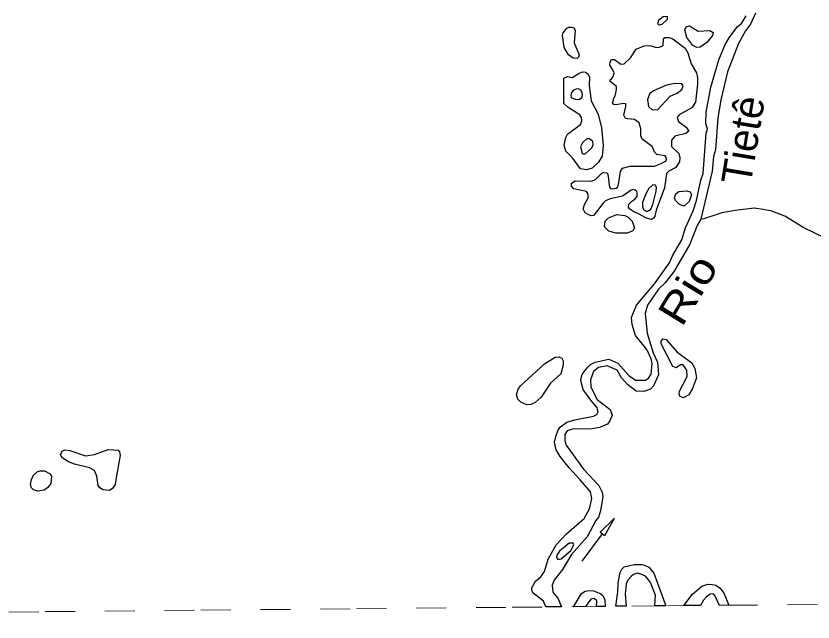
# Model space of a CAD drawing. Extents: x 346.5 to 372.4, y 7400.3 to 7428.2.
# Drawn here: x 361.849 to 364.517, y 7400.435 to 7402.464 of the extents above; entities that cross this region are included whole.
import ezdxf
from ezdxf.enums import TextEntityAlignment as Align

# ---------------------------------------------------------------- set-up
doc = ezdxf.new("R2010")
doc.units = 0
doc.header["$LTSCALE"] = 0.032
doc.linetypes.add('SHORT_DASHED', pattern=[2.7, 1.5, -1.2])
for name, color, linetype, lineweight in [('10', 7, 'Continuous', 25), ('2', 7, 'Continuous', 25), ('53', 7, 'SHORT_DASHED', 13), ('7', 7, 'Continuous', 25)]:
    doc.layers.add(name, color=color, linetype=linetype, lineweight=lineweight)
doc.layers.add('61', color=7, linetype='Continuous')

msp = doc.modelspace()

# ---------------------------------------------------------------- linework, layer by layer
at = {"layer": '10'}
msp.add_line((363.7437, 7400.6394), (363.8123, 7400.7301), dxfattribs=at)
msp.add_lwpolyline([(363.8526, 7400.7834), (363.8048, 7400.7359), (363.8199, 7400.7244)], close=True, dxfattribs=at)
at = {"layer": '2'}
for points in [[(364.3242, 7402.4731), (364.3184, 7402.4604), (364.3078, 7402.4359), (364.2912, 7402.4137), (364.2675, 7402.3718), (364.23, 7402.2764), (364.2086, 7402.183), (364.1981, 7402.1215), (364.1905, 7402.0154), (364.1833, 7401.9939), (364.1787, 7401.9447), (364.1416, 7401.7836), (364.1286, 7401.7624), (364.1045, 7401.6998), (364.0522, 7401.6091), (364.022, 7401.5709), (364, 7401.5495), (363.9624, 7401.496), (363.9552, 7401.4676), (363.9615, 7401.4019), (363.9814, 7401.3367), (363.9963, 7401.3045), (364, 7401.2624), (363.9834, 7401.226), (363.9725, 7401.215), (363.9505, 7401.2066), (363.9248, 7401.2083), (363.8953, 7401.2306), (363.8761, 7401.2527), (363.8618, 7401.2784), (363.828, 7401.2931), (363.799, 7401.2875), (363.7823, 7401.2734), (363.7715, 7401.2459), (363.7737, 7401.2214), (363.7939, 7401.1805), (363.8381, 7401.1462), (363.8447, 7401.1282), (363.8372, 7401.1087), (363.8287, 7401.0977), (363.8027, 7401.086), (363.7704, 7401.0811), (363.7148, 7401.0817), (363.6944, 7401.0747), (363.6861, 7401.0626), (363.6859, 7401.0415), (363.6911, 7401.0273), (363.7486, 7400.9474), (363.7996, 7400.8926), (363.8109, 7400.8698), (363.8137, 7400.8549), (363.8058, 7400.8072), (363.7985, 7400.7858), (363.7896, 7400.7755), (363.7612, 7400.7208), (363.7087, 7400.661), (363.6786, 7400.6106), (363.65, 7400.575), (363.6438, 7400.5587), (363.6463, 7400.5351), (363.6625, 7400.5148), (363.6752, 7400.4862), (363.6224, 7400.4857), (363.6143, 7400.5054), (363.579, 7400.5329), (363.5752, 7400.5414), (363.5757, 7400.5503), (363.5881, 7400.5716), (363.6054, 7400.5866), (363.6185, 7400.6042), (363.6305, 7400.6461), (363.6571, 7400.6934), (363.6919, 7400.7306), (363.7505, 7400.7817), (363.7686, 7400.8145), (363.7768, 7400.8493), (363.7718, 7400.8712), (363.7375, 7400.9111), (363.7008, 7400.9509), (363.6706, 7400.9891), (363.6575, 7401.0114), (363.6517, 7401.0373), (363.6557, 7401.0568), (363.6633, 7401.0784), (363.6719, 7401.0886), (363.693, 7401.1044), (363.7195, 7401.1124), (363.7825, 7401.1238), (363.7937, 7401.1304), (363.7979, 7401.1389), (363.7948, 7401.1518), (363.7727, 7401.1777)], [(363.7727, 7401.1777), (363.747, 7401.2141), (363.7408, 7401.2391), (363.7398, 7401.2471), (363.7442, 7401.2633), (363.7593, 7401.2855), (363.7722, 7401.2974), (363.7879, 7401.3051), (363.8331, 7401.3147), (363.8636, 7401.3015), (363.9002, 7401.2605), (363.9231, 7401.245), (363.9558, 7401.2445), (363.966, 7401.252), (363.9748, 7401.2649), (363.978, 7401.3001), (363.975, 7401.3157), (363.961, 7401.3479), (363.9228, 7401.3941), (363.9114, 7401.4308), (363.9092, 7401.4542), (363.9265, 7401.4958), (363.9864, 7401.5667), (364.0363, 7401.6373), (364.0467, 7401.6614), (364.0778, 7401.7143), (364.09, 7401.7544), (364.1156, 7401.8121), (364.1272, 7401.8462), (364.1415, 7401.9146), (364.1496, 7401.9362), (364.1588, 7402.0716), (364.1635, 7402.0847), (364.1584, 7402.1037), (364.159, 7402.1414), (364.1752, 7402.2259), (364.2019, 7402.3166), (364.2232, 7402.3682), (364.2359, 7402.3908), (364.2639, 7402.4282), (364.2772, 7402.4382), (364.2931, 7402.4645)], [(363.8457, 7402.173), (363.8475, 7402.1782), (363.8506, 7402.1888), (363.8549, 7402.197), (363.8584, 7402.2104), (363.8595, 7402.2202), (363.8592, 7402.2279), (363.8378, 7402.2448), (363.8378, 7402.2496), (363.8435, 7402.2542), (363.8481, 7402.2614), (363.8515, 7402.2734), (363.8466, 7402.2831), (363.8366, 7402.299), (363.838, 7402.3097), (363.8419, 7402.3179), (363.8525, 7402.3175), (363.8741, 7402.3028), (363.8843, 7402.3037), (363.9062, 7402.3239), (363.9254, 7402.3525), (363.9512, 7402.3642), (363.9711, 7402.3648), (363.9933, 7402.3586), (364.0027, 7402.3591), (364.0152, 7402.3654), (364.0166, 7402.388), (364.0213, 7402.392), (364.035, 7402.3916), (364.0475, 7402.3873), (364.0884, 7402.3563), (364.0981, 7402.34), (364.1093, 7402.3034), (364.1264, 7402.2735), (364.1303, 7402.2575), (364.13, 7402.2354), (364.1235, 7402.175), (364.1106, 7402.1566), (364.0687, 7402.1331), (364.0619, 7402.124), (364.0661, 7402.1111), (364.0925, 7402.0918), (364.1006, 7402.0785), (364.091, 7402.0708), (364.0545, 7402.0617), (364.0434, 7402.0485), (364.0428, 7402.0273), (364.0674, 7402.0029), (364.0715, 7401.9886), (364.0697, 7401.9754), (364.0579, 7401.9567), (364.0339, 7401.9438), (364.0268, 7401.9365), (364.0202, 7401.8884), (363.9923, 7401.8142), (363.9889, 7401.7994), (363.9868, 7401.7931), (363.9829, 7401.7867), (363.9757, 7401.7828), (363.9592, 7401.7873), (363.9326, 7401.8019), (363.9174, 7401.8083), (363.9037, 7401.8172), (363.8996, 7401.8231), (363.9005, 7401.834), (363.9103, 7401.844), (363.9207, 7401.8505), (363.9286, 7401.8598), (363.9287, 7401.8716), (363.9268, 7401.8767), (363.9212, 7401.8806), (363.9145, 7401.883), (363.9084, 7401.8812), (363.8793, 7401.8603), (363.8378, 7401.8513), (363.8226, 7401.8446), (363.8128, 7401.8362), (363.7877, 7401.8022), (363.7824, 7401.7961), (363.7733, 7401.7946), (363.7664, 7401.7984), (363.7544, 7401.8044), (363.747, 7401.8182), (363.7519, 7401.8322), (363.7655, 7401.8574), (363.7636, 7401.8693), (363.759, 7401.8764), (363.7161, 7401.8849), (363.708, 7401.8945), (363.708, 7401.9037), (363.7206, 7401.9118), (363.7744, 7401.9111), (363.7885, 7401.9167), (363.8097, 7401.9374), (363.8157, 7401.9395), (363.8274, 7401.9386), (363.8305, 7401.9331), (363.8308, 7401.9254), (363.8352, 7401.8907), (363.8395, 7401.8862), (363.8469, 7401.8849)], [(363.8469, 7401.8849), (363.858, 7401.8874), (363.8631, 7401.8914), (363.8674, 7401.9068), (363.8719, 7401.9437), (363.8795, 7401.9539), (363.9048, 7401.9606), (363.9862, 7401.9611), (364.0085, 7401.9698), (364.0204, 7401.9765), (364.0236, 7401.978), (364.0267, 7401.9843), (364.0256, 7401.9906), (364.0218, 7401.9951), (363.9938, 7402.0003), (363.9872, 7402.0069), (363.9786, 7402.0264), (363.9447, 7402.0517), (363.9404, 7402.0621), (363.94, 7402.0861), (363.9348, 7402.1057), (363.919, 7402.1176), (363.8969, 7402.1195), (363.8892, 7402.1206), (363.8841, 7402.132), (363.8906, 7402.1613), (363.8898, 7402.1699), (363.8821, 7402.1713), (363.864, 7402.1679), (363.8572, 7402.1662), (363.8503, 7402.1673), (363.8457, 7402.173)]]:
    msp.add_lwpolyline(points, dxfattribs=at)
for points in [[(364.0291, 7402.4522), (364.0103, 7402.4349), (364.0021, 7402.4333), (363.9972, 7402.4376), (364.0003, 7402.4509), (364.0152, 7402.4624), (364.0285, 7402.4626)], [(363.6923, 7402.4224), (363.6992, 7402.4263), (363.7094, 7402.4267), (363.7158, 7402.4237), (363.7207, 7402.4161), (363.7169, 7402.3741), (363.7339, 7402.334), (363.7324, 7402.3259), (363.7271, 7402.3212), (363.7142, 7402.3222), (363.6986, 7402.3332), (363.6839, 7402.3585), (363.6784, 7402.3981), (363.6811, 7402.4078)], [(364.1822, 7402.4085), (364.1803, 7402.3986), (364.1615, 7402.375), (364.139, 7402.3597), (364.1277, 7402.358), (364.115, 7402.3648), (364.0942, 7402.3918), (364.0877, 7402.4177), (364.0926, 7402.4272), (364.1032, 7402.4303), (364.1321, 7402.413), (364.1716, 7402.415)], [(363.8085, 7402.0888), (363.8143, 7402.0303), (363.8107, 7401.9945), (363.7989, 7401.974), (363.7774, 7401.9546), (363.7588, 7401.9493), (363.7387, 7401.9522), (363.7118, 7401.9884), (363.6894, 7402.0114), (363.6837, 7402.0317), (363.6894, 7402.0568), (363.6954, 7402.0681), (363.7387, 7402.1007), (363.7433, 7402.1112), (363.7418, 7402.1236), (363.7367, 7402.1327), (363.6972, 7402.1573), (363.6829, 7402.1711), (363.6826, 7402.2409), (363.6827, 7402.2555), (363.695, 7402.2617), (363.7105, 7402.2582), (363.7338, 7402.2728), (363.7464, 7402.2771), (363.7553, 7402.2759), (363.7641, 7402.2685), (363.7684, 7402.2584), (363.7675, 7402.2309), (363.7741, 7402.1799), (363.7982, 7402.1352)], [(364.0391, 7402.1951), (364.0617, 7402.2052), (364.078, 7402.2173), (364.0825, 7402.2294), (364.0778, 7402.237), (364.0546, 7402.2382), (364.0265, 7402.2325), (363.9829, 7402.2133), (363.9707, 7402.2045), (363.9627, 7402.1837), (363.9663, 7402.1606), (363.9782, 7402.1494), (363.9971, 7402.1512)], [(363.7066, 7402.1959), (363.7073, 7402.1911), (363.7149, 7402.1876), (363.7219, 7402.1848), (363.7281, 7402.1841), (363.735, 7402.1848), (363.7427, 7402.1904), (363.7454, 7402.198), (363.7441, 7402.2071), (363.7399, 7402.2154), (363.7323, 7402.2195), (363.7246, 7402.2189), (363.7149, 7402.2154), (363.7087, 7402.2077)], [(363.7391, 7402.0263), (363.7438, 7402.0049), (363.7478, 7402.0018), (363.7538, 7402.0026), (363.7761, 7402.0219), (363.7807, 7402.0327), (363.7801, 7402.0432), (363.7687, 7402.0521), (363.7596, 7402.0523), (363.7457, 7402.0395)], [(363.9464, 7401.8246), (363.9507, 7401.8146), (363.96, 7401.8095), (363.9695, 7401.8133), (363.9737, 7401.8171), (363.9811, 7401.8327), (363.9917, 7401.8769), (363.9928, 7401.8895), (363.9898, 7401.8979), (363.9807, 7401.8982), (363.9672, 7401.8868), (363.9583, 7401.8711), (363.9461, 7401.839)], [(364.0855, 7401.8272), (364.0694, 7401.8325), (364.057, 7401.8459), (364.0535, 7401.8549), (364.0574, 7401.8684), (364.0675, 7401.8763), (364.0949, 7401.8787), (364.1061, 7401.875), (364.1101, 7401.8649), (364.1026, 7401.8432)], [(363.8329, 7401.7438), (363.8191, 7401.7585), (363.8211, 7401.7771), (363.832, 7401.788), (363.8604, 7401.7991), (363.887, 7401.7954), (363.8986, 7401.7905), (363.911, 7401.7769), (363.9191, 7401.7548), (363.9142, 7401.7441), (363.8945, 7401.737), (363.8568, 7401.7363)], [(364.1262, 7401.253), (364.1136, 7401.2164), (364.1006, 7401.1954), (364.0822, 7401.1858), (364.0712, 7401.1915), (364.0683, 7401.1993), (364.0699, 7401.2077), (364.0953, 7401.2574), (364.0948, 7401.2784), (364.081, 7401.2974), (364.0733, 7401.296), (364.0586, 7401.2857), (364.0477, 7401.2902), (364.0087, 7401.3659), (364.0086, 7401.3743), (364.0143, 7401.3834), (364.0255, 7401.3807), (364.0609, 7401.3395), (364.111, 7401.3028), (364.1217, 7401.2836)], [(363.6384, 7401.2351), (363.607, 7401.1875), (363.5873, 7401.17), (363.5719, 7401.163), (363.5594, 7401.1621), (363.5389, 7401.1708), (363.5294, 7401.181), (363.5246, 7401.1964), (363.5296, 7401.215), (363.5376, 7401.2263), (363.6176, 7401.3), (363.6533, 7401.3221), (363.6664, 7401.3233), (363.6759, 7401.3188), (363.6809, 7401.3091), (363.6807, 7401.2954), (363.6731, 7401.2662)], [(362.1861, 7400.9246), (362.1817, 7400.8961), (362.1729, 7400.8819), (362.1609, 7400.8755), (362.1409, 7400.8782), (362.1305, 7400.8847), (362.125, 7400.8923), (362.12, 7400.9239), (362.1125, 7400.942), (362.0954, 7400.9511), (362.0449, 7400.9634), (362.0253, 7400.9714), (362.0042, 7400.9846), (361.9981, 7400.9953), (362.0037, 7401.0076), (362.0132, 7401.0113), (362.0302, 7401.0098), (362.082, 7400.9914), (362.1118, 7400.9964), (362.1577, 7401.0125), (362.191, 7401.0108), (362.1964, 7401.0046), (362.1977, 7400.9922)], [(361.9682, 7400.9239), (361.9657, 7400.899), (361.9558, 7400.8853), (361.9441, 7400.8762), (361.9218, 7400.8734), (361.9077, 7400.8782), (361.9015, 7400.8844), (361.8986, 7400.896), (361.9011, 7400.9124), (361.9086, 7400.9271), (361.9204, 7400.9377), (361.9306, 7400.9416), (361.9454, 7400.9408), (361.9641, 7400.9318)], [(363.6684, 7400.6727), (363.6596, 7400.6592), (363.6583, 7400.6508), (363.6632, 7400.6447), (363.6734, 7400.6465), (363.7057, 7400.6747), (363.7168, 7400.6938), (363.7138, 7400.6994), (363.7011, 7400.6989)], [(363.8572, 7400.4879), (363.8635, 7400.5365), (363.8647, 7400.5667), (363.8709, 7400.6012), (363.8771, 7400.6117), (363.8846, 7400.6204), (363.9186, 7400.6283), (363.9441, 7400.6273), (363.9522, 7400.6251), (363.9672, 7400.6188), (363.9798, 7400.6046), (363.9839, 7400.5983), (364.0238, 7400.4894), (363.9871, 7400.4891), (363.9891, 7400.5251), (363.9726, 7400.5671), (363.9659, 7400.5763), (363.9559, 7400.5886), (363.9403, 7400.5954), (363.9291, 7400.5988), (363.916, 7400.5946), (363.9076, 7400.5875), (363.8974, 7400.5757), (363.8916, 7400.5626), (363.8901, 7400.5487), (363.8876, 7400.5311), (363.8916, 7400.4882)], [(364.084, 7400.4901), (364.1137, 7400.5291), (364.1445, 7400.5557), (364.1648, 7400.5618), (364.1794, 7400.5612), (364.1912, 7400.559), (364.2057, 7400.5488), (364.218, 7400.5317), (364.2355, 7400.4914), (364.2034, 7400.4911), (364.1885, 7400.5245), (364.1837, 7400.5295), (364.173, 7400.5289), (364.1607, 7400.5196), (364.15, 7400.5083), (364.1406, 7400.4906)], [(363.7155, 7400.4865), (363.7418, 7400.5312), (363.7545, 7400.5391), (363.7673, 7400.5408), (363.783, 7400.5397), (363.795, 7400.5344), (363.8029, 7400.5316), (363.8129, 7400.5237), (363.8201, 7400.5101), (363.8214, 7400.4875), (363.7921, 7400.4872), (363.7935, 7400.5064), (363.7838, 7400.5146), (363.7732, 7400.5118), (363.7551, 7400.4869)]]:
    msp.add_lwpolyline(points, close=True, dxfattribs=at)
at = {"layer": '53'}
msp.add_lwpolyline([(358.2999, 7400.4352), (358.8209, 7400.4403), (359.3419, 7400.4453), (359.863, 7400.4502), (360.384, 7400.4552), (360.905, 7400.4602), (361.426, 7400.4651), (361.947, 7400.47), (362.4681, 7400.4749), (362.9891, 7400.4798), (363.5101, 7400.4846), (364.0311, 7400.4895), (364.5521, 7400.4943)], dxfattribs=at)
at = {"layer": '7'}
msp.add_lwpolyline([(365.1011, 7401.5269), (365.0777, 7401.5345), (364.9879, 7401.594), (364.9656, 7401.6012), (364.8811, 7401.5996), (364.8353, 7401.6058), (364.8085, 7401.6113), (364.7783, 7401.6227), (364.6954, 7401.6713), (364.5894, 7401.704), (364.4858, 7401.755), (364.4221, 7401.7933), (364.379, 7401.8108), (364.3503, 7401.8164), (364.3201, 7401.8204), (364.2563, 7401.8132), (364.2117, 7401.8052), (364.1518, 7401.7845), (364.1416, 7401.7836)], dxfattribs=at)

# ---------------------------------------------------------------- texts
at = {"layer": '61'}
msp.add_text('Tietê', height=0.1, rotation=80.538, dxfattribs=at).set_placement((364.3317, 7402.0398), align=Align.CENTER)
at = {"layer": '61', "width": 1.2}
msp.add_text('Rio', height=0.1, rotation=58.515, dxfattribs=at).set_placement((364.1404, 7401.5217), align=Align.CENTER)

doc.saveas('drawing.dxf')
